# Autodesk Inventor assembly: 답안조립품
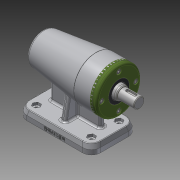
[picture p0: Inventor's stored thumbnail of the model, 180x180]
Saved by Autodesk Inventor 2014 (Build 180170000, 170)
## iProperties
Created: 2017-01
Part Number: 답안조립품
Document SubType Name: Assembly
Designer: owner
Author: owner
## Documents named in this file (9)
- C:\Users\owner\Desktop\470107V1007\답안조립품.iam
- C:\Users\owner\Desktop\470107V1007\본체.ipt
- C:\Users\owner\Desktop\470107V1007\베어링 51202.ipt
- C:\Users\owner\Desktop\470107V1007\어댑터슬리브.ipt
- C:\Users\owner\Desktop\470107V1007\베어링 6004.ipt
- C:\Users\owner\Desktop\470107V1007\축.ipt
- C:\Users\owner\Desktop\470107V1007\볼트 M4 x 12.ipt
- C:\Users\owner\Desktop\470107V1007\커버.ipt
- C:\Users\owner\Desktop\470107V1007\오일 실.ipt
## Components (5 placed, 1 different names)
1. ISO 4762 M4 x 12:1
2. ISO 4762 M4 x 12:2
3. ISO 4762 M4 x 12:3
4. ISO 4762 M4 x 12:4
5. ISO 4762 M4 x 12:5
